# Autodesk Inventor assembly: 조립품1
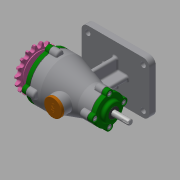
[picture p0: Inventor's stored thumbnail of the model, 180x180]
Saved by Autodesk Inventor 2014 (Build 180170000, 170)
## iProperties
Created: 2020-12
Part Number: 조립품1
Document SubType Name: Assembly
Designer: kh
Author: kh
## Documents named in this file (15)
- C:\Users\kh\Desktop\701206V1027\조립품1.iam
- C:\Users\kh\Desktop\701206V1027\본체.ipt
- C:\Users\kh\Desktop\701206V1027\개스킷 A.ipt
- C:\Users\kh\Desktop\701206V1027\개스킷 B.ipt
- C:\Users\kh\Desktop\701206V1027\앞커버.ipt
- C:\Users\kh\Desktop\701206V1027\베어링 6203.ipt
- C:\Users\kh\Desktop\701206V1027\오일 실 17 30 8.ipt
- C:\Users\kh\Desktop\701206V1027\축.ipt
- C:\Users\kh\Desktop\701206V1027\키 4x4x14.ipt
- C:\Users\kh\Desktop\701206V1027\뒤커버.ipt
- C:\Users\kh\Desktop\701206V1027\베어링 6200.ipt
- C:\Users\kh\Desktop\701206V1027\오일 실 10 20 7.ipt
- C:\Users\kh\Desktop\701206V1027\마개.ipt
- C:\Users\kh\Desktop\701206V1027\스프로킷.ipt
- C:\Users\kh\Desktop\701206V1027\볼트 M5.ipt
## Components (2 placed, 2 different names)
1. 개스킷 A:1
2. 개스킷 B:1
